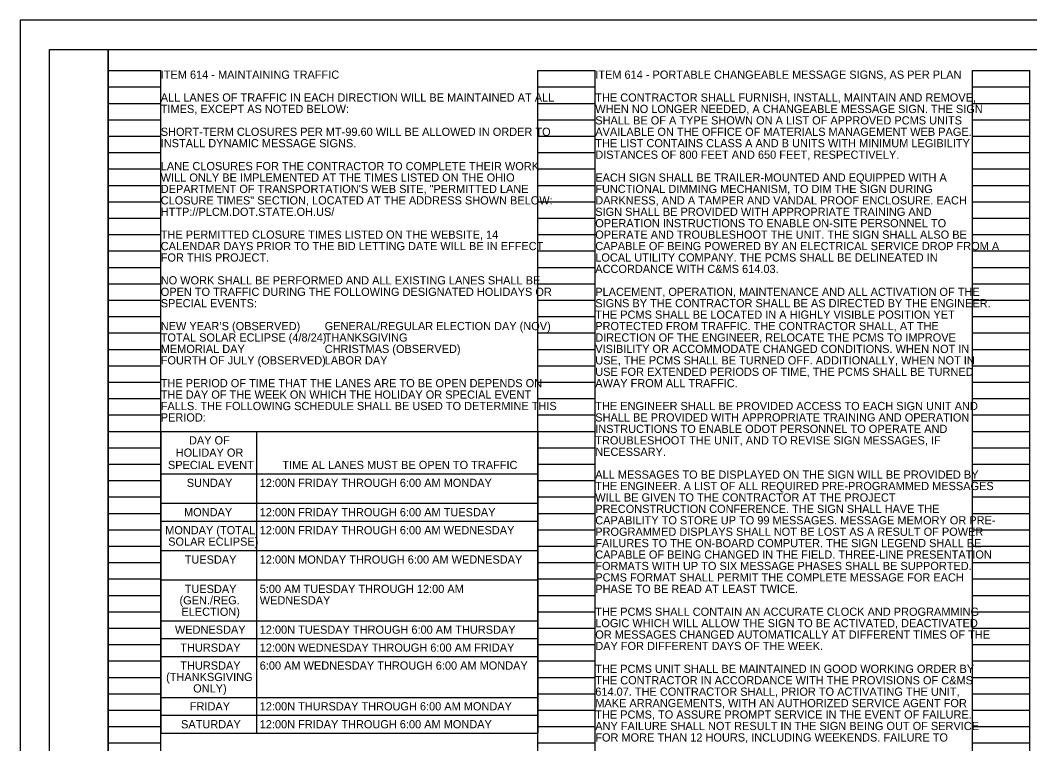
# Model space of a CAD drawing. Extents: x 0 to 34, y 0 to 22.
# Drawn here: x 0 to 17.24, y 9.65 to 22 of the extents above; entities that cross this region are included whole.
import ezdxf

# ---------------------------------------------------------------- set-up
doc = ezdxf.new("R2010")
doc.units = 0
for name, color, linetype in [('SH_Border', 7, 'Continuous'), ('SH_Cut_Line', 7, 'Continuous'), ('SH_Data', 7, 'Continuous'), ('SH_Text', 7, 'Continuous')]:
    doc.layers.add(name, color=color, linetype=linetype)

msp = doc.modelspace()

# ---------------------------------------------------------------- linework, layer by layer
at = {"layer": 'SH_Border'}
for points in [[(0.5, 21.5), (1.5, 21.5), (1.5, 0.5), (0.5, 0.5)], [(1.5, 21.5), (33.5, 21.5), (33.5, 0.5), (1.5, 0.5)]]:
    msp.add_lwpolyline(points, close=True, dxfattribs=at)
at = {"layer": 'SH_Cut_Line'}
msp.add_lwpolyline([(0, 0), (34, 0), (34, 22), (0, 22)], close=True, dxfattribs=at)
at = {"layer": 'SH_Data'}
for p, q in [((1.5, 0.98), (1.5, 21.14)), ((1.5, 21.14), (2.4, 21.14)), ((2.4, 0.98), (2.4, 21.14)), ((8.84, 0.98), (8.84, 21.14)), ((8.84, 21.14), (9.82, 21.14)), ((9.82, 0.98), (9.82, 21.14)), ((16.26, 0.98), (16.26, 21.14)), ((16.26, 21.14), (17.24, 21.14)), ((17.24, 0.98), (17.24, 21.14)), ((1.5, 20.86), (2.4, 20.86)), ((8.84, 20.86), (9.82, 20.86)), ((16.26, 20.86), (17.24, 20.86)), ((1.5, 20.58), (2.4, 20.58)), ((8.84, 20.58), (9.82, 20.58)), ((16.26, 20.58), (17.24, 20.58)), ((1.5, 20.3), (2.4, 20.3)), ((8.84, 20.3), (9.82, 20.3)), ((16.26, 20.3), (17.24, 20.3)), ((1.5, 20.02), (2.4, 20.02)), ((8.84, 20.02), (9.82, 20.02)), ((16.26, 20.02), (17.24, 20.02)), ((1.5, 19.74), (2.4, 19.74)), ((8.84, 19.74), (9.82, 19.74)), ((16.26, 19.74), (17.24, 19.74)), ((1.5, 19.46), (2.4, 19.46)), ((8.84, 19.46), (9.82, 19.46)), ((16.26, 19.46), (17.24, 19.46)), ((1.5, 19.18), (2.4, 19.18)), ((8.84, 19.18), (9.82, 19.18)), ((16.26, 19.18), (17.24, 19.18)), ((1.5, 18.9), (2.4, 18.9)), ((8.84, 18.9), (9.82, 18.9)), ((16.26, 18.9), (17.24, 18.9)), ((1.5, 18.62), (2.4, 18.62)), ((8.84, 18.62), (9.82, 18.62)), ((16.26, 18.62), (17.24, 18.62)), ((1.5, 18.34), (2.4, 18.34)), ((8.84, 18.34), (9.82, 18.34)), ((16.26, 18.34), (17.24, 18.34)), ((1.5, 18.06), (2.4, 18.06)), ((8.84, 18.06), (9.82, 18.06)), ((16.26, 18.06), (17.24, 18.06)), ((1.5, 17.78), (2.4, 17.78)), ((8.84, 17.78), (9.82, 17.78)), ((16.26, 17.78), (17.24, 17.78)), ((1.5, 17.5), (2.4, 17.5)), ((8.84, 17.5), (9.82, 17.5)), ((16.26, 17.5), (17.24, 17.5)), ((1.5, 17.22), (2.4, 17.22)), ((8.84, 17.22), (9.82, 17.22)), ((16.26, 17.22), (17.24, 17.22)), ((1.5, 16.94), (2.4, 16.94)), ((8.84, 16.94), (9.82, 16.94)), ((16.26, 16.94), (17.24, 16.94)), ((1.5, 16.66), (2.4, 16.66)), ((8.84, 16.66), (9.82, 16.66)), ((16.26, 16.66), (17.24, 16.66)), ((1.5, 16.38), (2.4, 16.38)), ((8.84, 16.38), (9.82, 16.38)), ((16.26, 16.38), (17.24, 16.38)), ((1.5, 16.1), (2.4, 16.1)), ((8.84, 16.1), (9.82, 16.1)), ((16.26, 16.1), (17.24, 16.1)), ((1.5, 15.82), (2.4, 15.82)), ((8.84, 15.82), (9.82, 15.82)), ((16.26, 15.82), (17.24, 15.82)), ((1.5, 15.54), (2.4, 15.54)), ((8.84, 15.54), (9.82, 15.54)), ((16.26, 15.54), (17.24, 15.54)), ((1.5, 15.26), (2.4, 15.26)), ((8.84, 15.26), (9.82, 15.26)), ((16.26, 15.26), (17.24, 15.26)), ((1.5, 14.98), (2.4, 14.98)), ((8.84, 14.98), (9.82, 14.98)), ((16.26, 14.98), (17.24, 14.98)), ((1.5, 14.7), (2.4, 14.7)), ((8.84, 14.7), (9.82, 14.7)), ((16.26, 14.7), (17.24, 14.7)), ((1.5, 14.42), (2.4, 14.42)), ((8.84, 14.42), (9.82, 14.42)), ((16.26, 14.42), (17.24, 14.42)), ((1.5, 14.14), (2.4, 14.14)), ((8.84, 14.14), (9.82, 14.14)), ((16.26, 14.14), (17.24, 14.14)), ((1.5, 13.86), (2.4, 13.86)), ((8.84, 13.86), (9.82, 13.86)), ((16.26, 13.86), (17.24, 13.86)), ((1.5, 13.58), (2.4, 13.58)), ((8.84, 13.58), (9.82, 13.58)), ((16.26, 13.58), (17.24, 13.58)), ((1.5, 13.3), (2.4, 13.3)), ((8.84, 13.3), (9.82, 13.3)), ((16.26, 13.3), (17.24, 13.3)), ((1.5, 13.02), (2.4, 13.02)), ((8.84, 13.02), (9.82, 13.02)), ((16.26, 13.02), (17.24, 13.02)), ((1.5, 12.74), (2.4, 12.74)), ((8.84, 12.74), (9.82, 12.74)), ((16.26, 12.74), (17.24, 12.74)), ((1.5, 12.46), (2.4, 12.46)), ((8.84, 12.46), (9.82, 12.46)), ((16.26, 12.46), (17.24, 12.46)), ((1.5, 12.18), (2.4, 12.18)), ((8.84, 12.18), (9.82, 12.18)), ((16.26, 12.18), (17.24, 12.18)), ((1.5, 11.9), (2.4, 11.9)), ((8.84, 11.9), (9.82, 11.9)), ((16.26, 11.9), (17.24, 11.9)), ((1.5, 11.62), (2.4, 11.62)), ((8.84, 11.62), (9.82, 11.62)), ((16.26, 11.62), (17.24, 11.62)), ((1.5, 11.34), (2.4, 11.34)), ((8.84, 11.34), (9.82, 11.34)), ((16.26, 11.34), (17.24, 11.34)), ((1.5, 11.06), (2.4, 11.06)), ((8.84, 11.06), (9.82, 11.06)), ((16.26, 11.06), (17.24, 11.06)), ((1.5, 10.78), (2.4, 10.78)), ((8.84, 10.78), (9.82, 10.78)), ((16.26, 10.78), (17.24, 10.78)), ((1.5, 10.5), (2.4, 10.5)), ((8.84, 10.5), (9.82, 10.5)), ((16.26, 10.5), (17.24, 10.5)), ((1.5, 10.22), (2.4, 10.22)), ((8.84, 10.22), (9.82, 10.22)), ((16.26, 10.22), (17.24, 10.22)), ((1.5, 9.94), (2.4, 9.94)), ((8.84, 9.94), (9.82, 9.94)), ((16.26, 9.94), (17.24, 9.94)), ((1.5, 9.66), (2.4, 9.66)), ((8.84, 9.66), (9.82, 9.66)), ((16.26, 9.66), (17.24, 9.66))]:
    msp.add_line(p, q, dxfattribs=at)
at = {"layer": 'SH_Text'}
for p, q in [((2.4, 14.98), (8.842, 14.98)), ((2.4, 14.98), (2.4, 9.827)), ((4.034, 14.98), (4.034, 9.827)), ((8.842, 14.98), (8.842, 9.827)), ((2.4, 14.254), (8.842, 14.254)), ((2.4, 13.753), (8.842, 13.753)), ((2.4, 13.446), (8.842, 13.446)), ((2.4, 12.945), (8.842, 12.945)), ((2.4, 12.444), (8.842, 12.444)), ((2.4, 11.748), (8.842, 11.748)), ((2.4, 11.441), (8.842, 11.441)), ((2.4, 11.135), (8.842, 11.135)), ((2.4, 10.439), (8.842, 10.439)), ((2.4, 10.133), (8.842, 10.133)), ((2.4, 9.827), (8.842, 9.827))]:
    msp.add_line(p, q, dxfattribs=at)

# ---------------------------------------------------------------- texts
for s, p in [('ITEM 614 - MAINTAINING TRAFFIC', (2.4, 21)), ('ITEM 614 - PORTABLE CHANGEABLE MESSAGE SIGNS, AS PER PLAN', (9.82, 21)), ('ALL LANES OF TRAFFIC IN EACH DIRECTION WILL BE MAINTAINED AT ALL ', (2.4, 20.61)), ('THE CONTRACTOR SHALL FURNISH, INSTALL, MAINTAIN AND REMOVE, ', (9.82, 20.61)), ('TIMES, EXCEPT AS NOTED BELOW:', (2.4, 20.415)), ('WHEN NO LONGER NEEDED, A CHANGEABLE MESSAGE SIGN. THE SIGN ', (9.82, 20.415)), ('SHALL BE OF A TYPE SHOWN ON A LIST OF APPROVED PCMS UNITS ', (9.82, 20.22)), ('SHORT-TERM CLOSURES PER MT-99.60 WILL BE ALLOWED IN ORDER TO ', (2.4, 20.025)), ('AVAILABLE ON THE OFFICE OF MATERIALS MANAGEMENT WEB PAGE. ', (9.82, 20.025)), ('INSTALL DYNAMIC MESSAGE SIGNS.', (2.4, 19.83)), ('THE LIST CONTAINS CLASS A AND B UNITS WITH MINIMUM LEGIBILITY ', (9.82, 19.83)), ('DISTANCES OF 800 FEET AND 650 FEET, RESPECTIVELY.  ', (9.82, 19.634)), ('LANE CLOSURES FOR THE CONTRACTOR TO COMPLETE THEIR WORK ', (2.4, 19.439)), ('WILL ONLY BE IMPLEMENTED AT THE TIMES LISTED ON THE OHIO ', (2.4, 19.244)), ('EACH SIGN SHALL BE TRAILER-MOUNTED AND EQUIPPED WITH A ', (9.82, 19.244)), ('DEPARTMENT OF TRANSPORTATION\'S WEB SITE, "PERMITTED LANE ', (2.4, 19.049)), ('FUNCTIONAL DIMMING MECHANISM, TO DIM THE SIGN DURING ', (9.82, 19.049)), ('CLOSURE TIMES" SECTION, LOCATED AT THE ADDRESS SHOWN BELOW:', (2.4, 18.854)), ('DARKNESS, AND A TAMPER AND VANDAL PROOF ENCLOSURE. EACH ', (9.82, 18.854)), ('HTTP://PLCM.DOT.STATE.OH.US/', (2.4, 18.659)), ('SIGN SHALL BE PROVIDED WITH APPROPRIATE TRAINING AND ', (9.82, 18.659)), ('OPERATION INSTRUCTIONS TO ENABLE ON-SITE PERSONNEL TO ', (9.82, 18.464)), ('THE PERMITTED CLOSURE TIMES LISTED ON THE WEBSITE, 14 ', (2.4, 18.269)), ('OPERATE AND TROUBLESHOOT THE UNIT. THE SIGN SHALL ALSO BE ', (9.82, 18.269)), ('CALENDAR DAYS PRIOR TO THE BID LETTING DATE WILL BE IN EFFECT ', (2.4, 18.074)), ('CAPABLE OF BEING POWERED BY AN ELECTRICAL SERVICE DROP FROM A ', (9.82, 18.074)), ('FOR THIS PROJECT.', (2.4, 17.879)), ('LOCAL UTILITY COMPANY. THE PCMS SHALL BE DELINEATED IN ', (9.82, 17.879)), ('ACCORDANCE WITH C&MS 614.03. ', (9.82, 17.684)), ('NO WORK SHALL BE PERFORMED AND ALL EXISTING LANES SHALL BE ', (2.4, 17.489)), ('OPEN TO TRAFFIC DURING THE FOLLOWING DESIGNATED HOLIDAYS OR ', (2.4, 17.293)), ('PLACEMENT, OPERATION, MAINTENANCE AND ALL ACTIVATION OF THE ', (9.82, 17.293)), ('SPECIAL EVENTS:', (2.4, 17.098)), ('SIGNS BY THE CONTRACTOR SHALL BE AS DIRECTED BY THE ENGINEER. ', (9.82, 17.098)), ('THE PCMS SHALL BE LOCATED IN A HIGHLY VISIBLE POSITION YET ', (9.82, 16.903)), ('NEW YEAR’S (OBSERVED)', (2.4, 16.708)), ('GENERAL/REGULAR ELECTION DAY (NOV)', (5.2, 16.708)), ('PROTECTED FROM TRAFFIC. THE CONTRACTOR SHALL, AT THE ', (9.82, 16.708)), ('TOTAL SOLAR ECLIPSE (4/8/24)', (2.4, 16.513)), ('THANKSGIVING', (5.2, 16.513)), ('DIRECTION OF THE ENGINEER, RELOCATE THE PCMS TO IMPROVE ', (9.82, 16.513)), ('MEMORIAL DAY', (2.4, 16.318)), ('CHRISTMAS (OBSERVED)', (5.2, 16.318)), ('VISIBILITY OR ACCOMMODATE CHANGED CONDITIONS. WHEN NOT IN ', (9.82, 16.318)), ('FOURTH OF JULY (OBSERVED)', (2.4, 16.123)), ('LABOR DAY', (5.2, 16.123)), ('USE, THE PCMS SHALL BE TURNED OFF. ADDITIONALLY, WHEN NOT IN ', (9.82, 16.123)), ('USE FOR EXTENDED PERIODS OF TIME, THE PCMS SHALL BE TURNED ', (9.82, 15.928)), ('THE PERIOD OF TIME THAT THE LANES ARE TO BE OPEN DEPENDS ON ', (2.4, 15.733)), ('AWAY FROM ALL TRAFFIC.  ', (9.82, 15.733)), ('THE DAY OF THE WEEK ON WHICH THE HOLIDAY OR SPECIAL EVENT ', (2.4, 15.538)), ('FALLS. THE FOLLOWING SCHEDULE SHALL BE USED TO DETERMINE THIS ', (2.4, 15.343)), ('THE ENGINEER SHALL BE PROVIDED ACCESS TO EACH SIGN UNIT AND ', (9.82, 15.343)), ('PERIOD:', (2.4, 15.148)), ('SHALL BE PROVIDED WITH APPROPRIATE TRAINING AND OPERATION ', (9.82, 15.148)), ('INSTRUCTIONS TO ENABLE ODOT PERSONNEL TO OPERATE AND ', (9.82, 14.953)), ('DAY OF ', (2.882, 14.757)), ('TROUBLESHOOT THE UNIT, AND TO REVISE SIGN MESSAGES, IF ', (9.82, 14.757)), ('HOLIDAY OR ', (2.656, 14.547)), ('NECESSARY.', (9.82, 14.562)), ('SPECIAL EVENT', (2.523, 14.337)), ('TIME AL LANES MUST BE OPEN TO TRAFFIC', (4.476, 14.337)), ('ALL MESSAGES TO BE DISPLAYED ON THE SIGN WILL BE PROVIDED BY ', (9.82, 14.172)), ('SUNDAY', (2.844, 14.031)), ('12:00N FRIDAY THROUGH 6:00 AM MONDAY', (4.09, 14.031)), ('THE ENGINEER. A LIST OF ALL REQUIRED PRE-PROGRAMMED MESSAGES ', (9.82, 13.977)), ('WILL BE GIVEN TO THE CONTRACTOR AT THE PROJECT ', (9.82, 13.782)), ('MONDAY', (2.798, 13.53)), ('12:00N FRIDAY THROUGH 6:00 AM TUESDAY', (4.09, 13.53)), ('PRECONSTRUCTION CONFERENCE. THE SIGN SHALL HAVE THE ', (9.82, 13.587)), ('CAPABILITY TO STORE UP TO 99 MESSAGES. MESSAGE MEMORY OR PRE-', (9.82, 13.392)), ('MONDAY (TOTAL ', (2.476, 13.223)), ('12:00N FRIDAY THROUGH 6:00 AM WEDNESDAY', (4.09, 13.223)), ('PROGRAMMED DISPLAYS SHALL NOT BE LOST AS A RESULT OF POWER ', (9.82, 13.197)), ('SOLAR ECLIPSE)', (2.527, 13.028)), ('FAILURES TO THE ON-BOARD COMPUTER. THE SIGN LEGEND SHALL BE ', (9.82, 13.002)), ('CAPABLE OF BEING CHANGED IN THE FIELD. THREE-LINE PRESENTATION ', (9.82, 12.807)), ('TUESDAY', (2.809, 12.722)), ('12:00N MONDAY THROUGH 6:00 AM WEDNESDAY', (4.09, 12.722)), ('FORMATS WITH UP TO SIX MESSAGE PHASES SHALL BE SUPPORTED. ', (9.82, 12.612)), ('PCMS FORMAT SHALL PERMIT THE COMPLETE MESSAGE FOR EACH ', (9.82, 12.417)), ('TUESDAY ', (2.809, 12.221)), ('5:00 AM TUESDAY THROUGH 12:00 AM ', (4.09, 12.221)), ('PHASE TO BE READ AT LEAST TWICE.', (9.82, 12.221)), ('(GEN./REG. ', (2.72, 12.026)), ('WEDNESDAY', (4.09, 12.026)), ('ELECTION)', (2.753, 11.831)), ('THE PCMS SHALL CONTAIN AN ACCURATE CLOCK AND PROGRAMMING ', (9.82, 11.831)), ('LOGIC WHICH WILL ALLOW THE SIGN TO BE ACTIVATED, DEACTIVATED ', (9.82, 11.636)), ('WEDNESDAY', (2.642, 11.525)), ('12:00N TUESDAY THROUGH 6:00 AM THURSDAY', (4.09, 11.525)), ('OR MESSAGES CHANGED AUTOMATICALLY AT DIFFERENT TIMES OF THE ', (9.82, 11.441)), ('DAY FOR DIFFERENT DAYS OF THE WEEK.', (9.82, 11.246)), ('THURSDAY', (2.734, 11.218)), ('12:00N WEDNESDAY THROUGH 6:00 AM FRIDAY', (4.09, 11.218)), ('THURSDAY ', (2.734, 10.912)), ('6:00 AM WEDNESDAY THROUGH 6:00 AM MONDAY', (4.09, 10.912)), ('(THANKSGIVING ', (2.492, 10.717)), ('THE PCMS UNIT SHALL BE MAINTAINED IN GOOD WORKING ORDER BY ', (9.82, 10.856)), ('THE CONTRACTOR IN ACCORDANCE WITH THE PROVISIONS OF C&MS ', (9.82, 10.661)), ('ONLY)', (2.954, 10.522)), ('614.07. THE CONTRACTOR SHALL, PRIOR TO ACTIVATING THE UNIT, ', (9.82, 10.466)), ('FRIDAY', (2.897, 10.216)), ('12:00N THURSDAY THROUGH 6:00 AM MONDAY', (4.09, 10.216)), ('MAKE ARRANGEMENTS, WITH AN AUTHORIZED SERVICE AGENT FOR ', (9.82, 10.271)), ('THE PCMS, TO ASSURE PROMPT SERVICE IN THE EVENT OF FAILURE. ', (9.82, 10.076)), ('SATURDAY', (2.747, 9.91)), ('12:00N FRIDAY THROUGH 6:00 AM MONDAY', (4.09, 9.91)), ('ANY FAILURE SHALL NOT RESULT IN THE SIGN BEING OUT OF SERVICE ', (9.82, 9.88)), ('FOR MORE THAN 12 HOURS, INCLUDING WEEKENDS. FAILURE TO ', (9.82, 9.685))]:
    msp.add_text(s, height=0.14, dxfattribs=at).set_placement(p)

doc.saveas('drawing.dxf')
